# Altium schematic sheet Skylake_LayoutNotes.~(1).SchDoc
size 431 x 279 mm; Date: Not shown in title block; ApprovedBy: Not shown in title block; CheckedBy: Not shown in title block; Author: Not shown in title block; CompanyName: Not shown in title block; Engineer: Not shown in title block; Organization: Not shown in title block; Address1: Not shown in title block; Address2: Not shown in title block; Address3: Not shown in title block; Address4: Not shown in title block; DocumentNumber: 1; Revision: Use project parameter SCH_Rev; SheetNumber: 9; SheetTotal: 9; PageSetup: Record=PageOptions|CenterHorizontal=True|CenterVertical=True|PrintScale=1.00|XCorrection=1.00|YCorrection=1.00|PrintKind=0|BorderSize=5000000|LeftOffset=0|BottomOffset=0|Orientation=2|PaperLength=1000|PaperWidth=1000|Scale=100|PaperSource=15|PrintQuality=600|MediaType=1|DitherType=10|PaperKind=Letter|PrintScaleMode=1
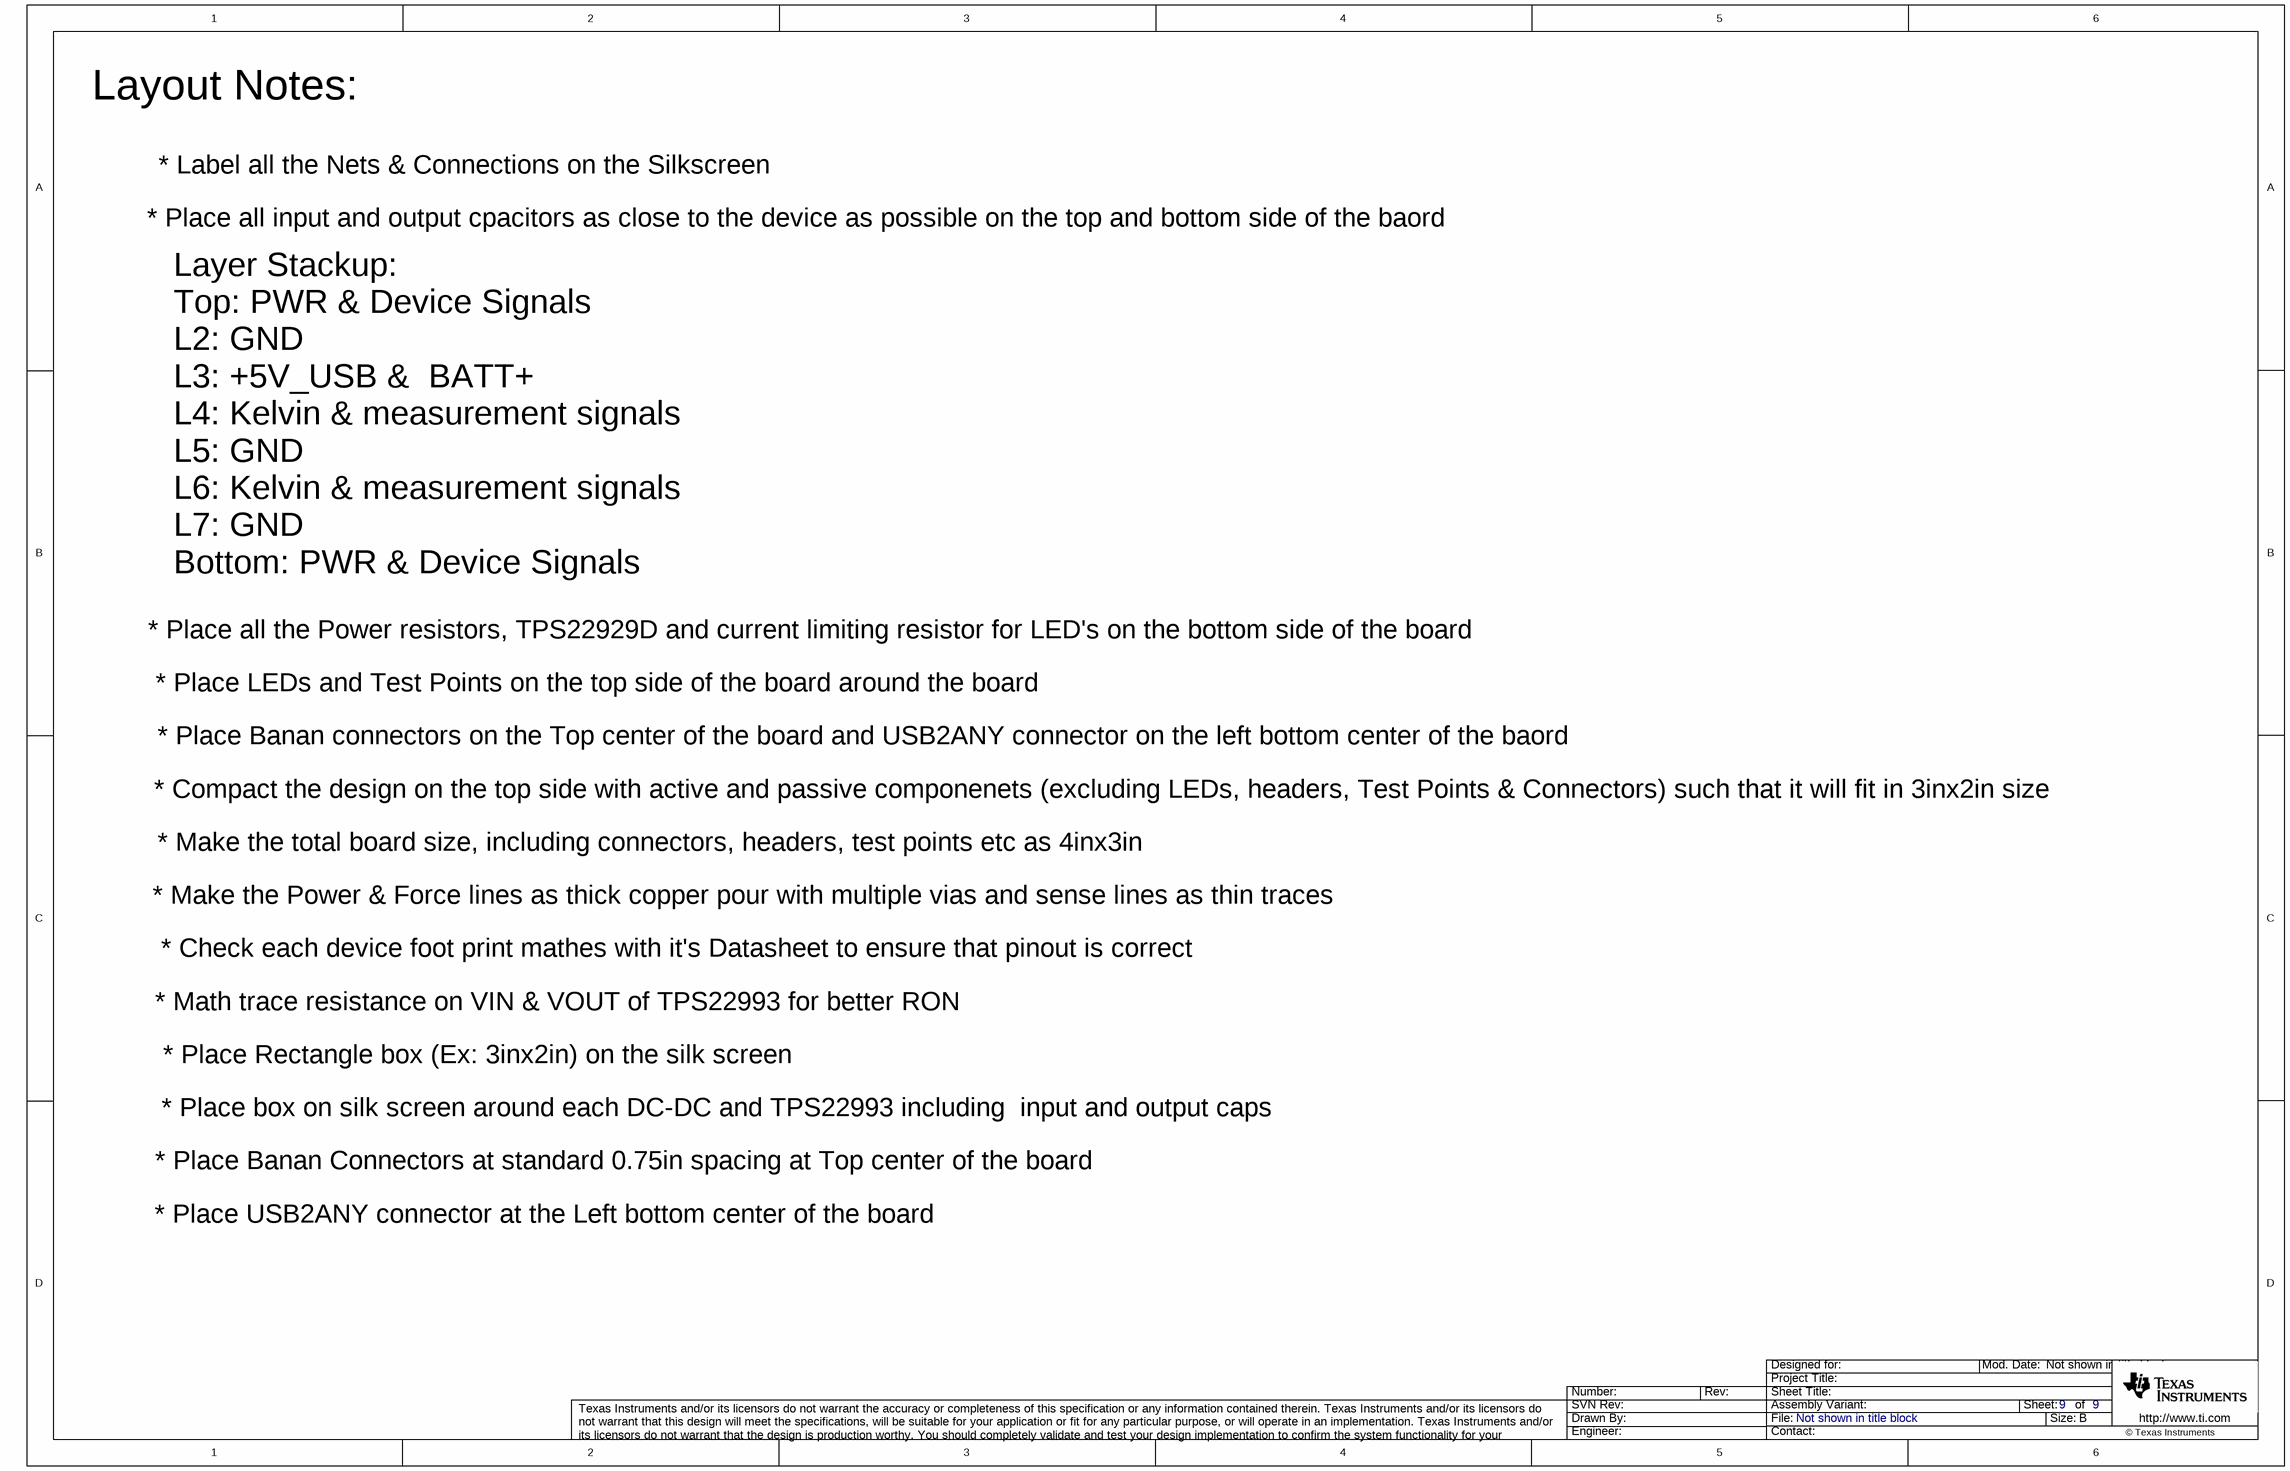
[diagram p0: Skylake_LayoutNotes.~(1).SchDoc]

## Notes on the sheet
- Layout Notes:
- * Label all the Nets & Connections on the Silkscreen
- * Place all input and output cpacitors as close to the device as possible on the top and bottom side of the baord
- Layer Stackup:
  Top: PWR & Device Signals
  L2: GND
  L3: +5V_USB &  BATT+
  L4: Kelvin & measurement signals
  L5: GND
  L6: Kelvin & measurement signals
  L7: GND
  Bottom: PWR & Device Signals
- * Place all the Power resistors, TPS22929D and current limiting resistor for LED's on the bottom side of the board
- * Place LEDs and Test Points on the top side of the board around the board
- * Place Banan connectors on the Top center of the board and USB2ANY connector on the left bottom center of the baord
- * Compact the design on the top side with active and passive componenets (excluding LEDs, headers, Test Points & Connectors) such that it will fit in 3inx2in size
- * Make the total board size, including connectors, headers, test points etc as 4inx3in
- * Make the Power & Force lines as thick copper pour with multiple vias and sense lines as thin traces
- * Check each device foot print mathes with it's Datasheet to ensure that pinout is correct
- * Math trace resistance on VIN & VOUT of TPS22993 for better RON
- * Place Rectangle box (Ex: 3inx2in) on the silk screen
- * Place Banan Connectors at standard 0.75in spacing at Top center of the board
- * Place box on silk screen around each DC-DC and TPS22993 including  input and output caps
- * Place USB2ANY connector at the Left bottom center of the board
